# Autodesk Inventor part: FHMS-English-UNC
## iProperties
Author: cdotson
Shininess: 25.0
PropertySet Name: _Private Model Information
Created: 2001-02
Part Number: FHMS-English-UNC
Material: Steel, Mild
Document SubType Name: Modeling
Designer: cdotson
Control State: 0
Master: False
Checked Out: False
PropertySet Name: Design Tracking Control
Density: 7.86
Volumn: 0.9570212615531521
Area: 7.706801682804725
PropertySet Name: Model Information
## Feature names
1. Extrusion1
2. Extrusion2
3. Extrusion3
4. Chamfer2
5. Fillet1
